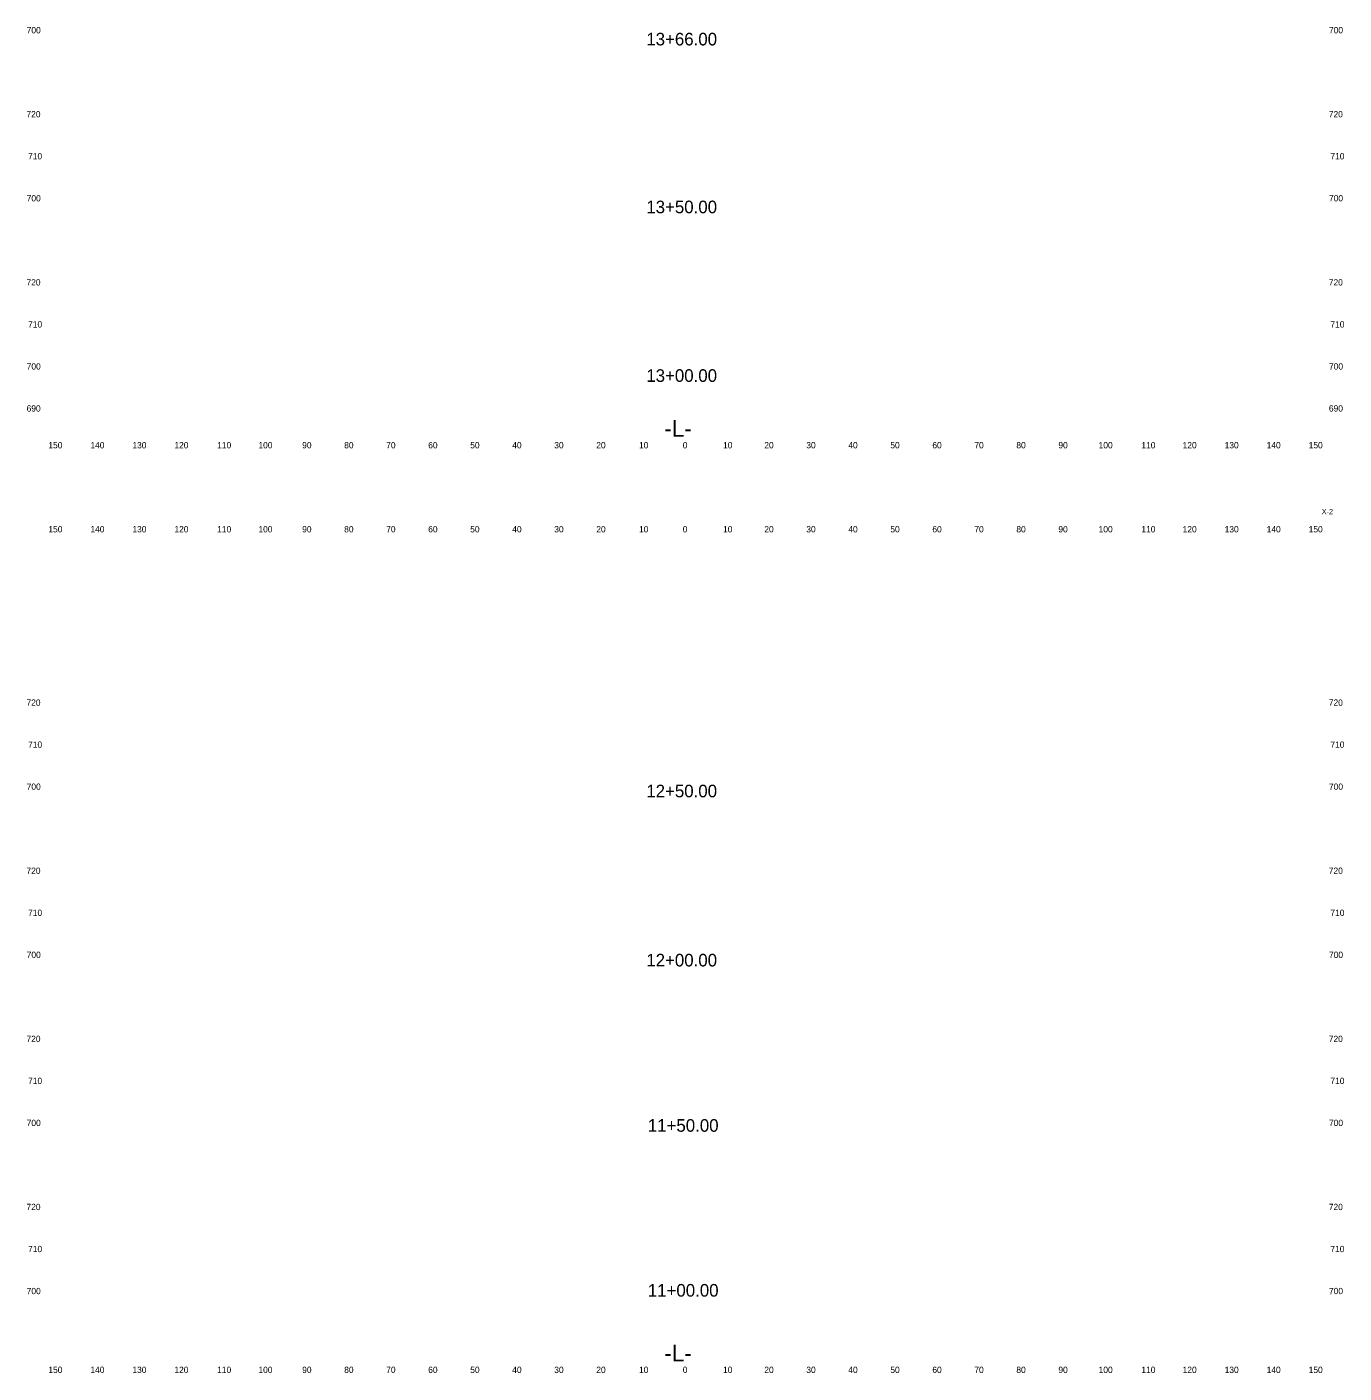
# Model space of a CAD drawing. Extents: x 3 to 317, y 1 to 1307.
# Drawn here: x 3.3 to 316.9, y 1.2 to 321.5 of the extents above; entities that cross this region are included whole.
import ezdxf

# ---------------------------------------------------------------- set-up
doc = ezdxf.new("R2010")
doc.units = 0
for name, color, linetype in [('Prop XS Alignment Label', 7, 'Continuous'), ('Prop XS Elevation Labels', 7, 'Continuous'), ('Prop XS Offset Labels', 7, 'Continuous'), ('Prop XS Sheet Number', 7, 'Continuous'), ('Prop XS Station Labels', 7, 'Continuous')]:
    doc.layers.add(name, color=color, linetype=linetype)

msp = doc.modelspace()

# ---------------------------------------------------------------- texts
at = {"layer": 'Prop XS Alignment Label'}
for p in [(155.06, 224), (155.06, 4)]:
    msp.add_text('-L-', height=4, dxfattribs=at).set_placement(p)
at = {"layer": 'Prop XS Elevation Labels'}
for s, p in [('700', (3.28, 320)), ('700', (313.28, 320)), ('720', (3.23, 300)), ('720', (313.23, 300)), ('710', (3.61, 290)), ('710', (313.61, 290)), ('700', (3.28, 280)), ('700', (313.28, 280)), ('720', (3.23, 260)), ('720', (313.23, 260)), ('710', (3.61, 250)), ('710', (313.61, 250)), ('700', (3.28, 240)), ('700', (313.28, 240)), ('690', (3.26, 230)), ('690', (313.26, 230)), ('720', (3.23, 160)), ('720', (313.23, 160)), ('710', (3.61, 150)), ('710', (313.61, 150)), ('700', (3.28, 140)), ('700', (313.28, 140)), ('720', (3.23, 120)), ('720', (313.23, 120)), ('710', (3.61, 110)), ('710', (313.61, 110)), ('700', (3.28, 100)), ('700', (313.28, 100)), ('720', (3.23, 80)), ('720', (313.23, 80)), ('710', (3.61, 70)), ('710', (313.61, 70)), ('700', (3.28, 60)), ('700', (313.28, 60)), ('720', (3.23, 40)), ('720', (313.23, 40)), ('710', (3.61, 30)), ('710', (313.61, 30)), ('700', (3.28, 20)), ('700', (313.28, 20))]:
    msp.add_text(s, height=1.5, dxfattribs=at).set_placement(p)
at = {"layer": 'Prop XS Offset Labels'}
for s, p in [('150', (8.44, 221.25)), ('140', (18.44, 221.25)), ('130', (28.44, 221.25)), ('120', (38.44, 221.25)), ('110', (48.62, 221.25)), ('100', (58.44, 221.25)), ('90', (68.86, 221.25)), ('80', (78.86, 221.25)), ('70', (88.86, 221.25)), ('60', (98.86, 221.25)), ('50', (108.86, 221.25)), ('40', (118.86, 221.25)), ('30', (128.86, 221.25)), ('20', (138.86, 221.25)), ('10', (149.04, 221.25)), ('0', (159.45, 221.25)), ('0', (159.45, 221.25)), ('10', (169.04, 221.25)), ('20', (178.86, 221.25)), ('30', (188.86, 221.25)), ('40', (198.86, 221.25)), ('50', (208.86, 221.25)), ('60', (218.86, 221.25)), ('70', (228.86, 221.25)), ('80', (238.86, 221.25)), ('90', (248.86, 221.25)), ('100', (258.44, 221.25)), ('110', (268.62, 221.25)), ('120', (278.44, 221.25)), ('130', (288.44, 221.25)), ('140', (298.44, 221.25)), ('150', (308.44, 221.25)), ('150', (8.44, 201.25)), ('140', (18.44, 201.25)), ('130', (28.44, 201.25)), ('120', (38.44, 201.25)), ('110', (48.62, 201.25)), ('100', (58.44, 201.25)), ('90', (68.86, 201.25)), ('80', (78.86, 201.25)), ('70', (88.86, 201.25)), ('60', (98.86, 201.25)), ('50', (108.86, 201.25)), ('40', (118.86, 201.25)), ('30', (128.86, 201.25)), ('20', (138.86, 201.25)), ('10', (149.04, 201.25)), ('0', (159.45, 201.25)), ('0', (159.45, 201.25)), ('10', (169.04, 201.25)), ('20', (178.86, 201.25)), ('30', (188.86, 201.25)), ('40', (198.86, 201.25)), ('50', (208.86, 201.25)), ('60', (218.86, 201.25)), ('70', (228.86, 201.25)), ('80', (238.86, 201.25)), ('90', (248.86, 201.25)), ('100', (258.44, 201.25)), ('110', (268.62, 201.25)), ('120', (278.44, 201.25)), ('130', (288.44, 201.25)), ('140', (298.44, 201.25)), ('150', (308.44, 201.25)), ('150', (8.44, 1.25)), ('140', (18.44, 1.25)), ('130', (28.44, 1.25)), ('120', (38.44, 1.25)), ('110', (48.62, 1.25)), ('100', (58.44, 1.25)), ('90', (68.86, 1.25)), ('80', (78.86, 1.25)), ('70', (88.86, 1.25)), ('60', (98.86, 1.25)), ('50', (108.86, 1.25)), ('40', (118.86, 1.25)), ('30', (128.86, 1.25)), ('20', (138.86, 1.25)), ('10', (149.04, 1.25)), ('0', (159.45, 1.25)), ('0', (159.45, 1.25)), ('10', (169.04, 1.25)), ('20', (178.86, 1.25)), ('30', (188.86, 1.25)), ('40', (198.86, 1.25)), ('50', (208.86, 1.25)), ('60', (218.86, 1.25)), ('70', (228.86, 1.25)), ('80', (238.86, 1.25)), ('90', (248.86, 1.25)), ('100', (258.44, 1.25)), ('110', (268.62, 1.25)), ('120', (278.44, 1.25)), ('130', (288.44, 1.25)), ('140', (298.44, 1.25)), ('150', (308.44, 1.25))]:
    msp.add_text(s, height=1.5, dxfattribs=at).set_placement(p)
at = {"layer": 'Prop XS Sheet Number'}
msp.add_text('X-2', height=1.25, dxfattribs=at).set_placement((311.56, 205.59))
at = {"layer": 'Prop XS Station Labels'}
for s, p in [('13+66.00', (150.77, 317.12)), ('13+50.00', (150.77, 277.19)), ('13+00.00', (150.77, 237.07)), ('12+50.00', (150.77, 138.22)), ('12+00.00', (150.77, 97.98)), ('11+50.00', (151.13, 58.65)), ('11+00.00', (151.13, 19.42))]:
    msp.add_text(s, height=3, dxfattribs=at).set_placement(p)

doc.saveas('drawing.dxf')
